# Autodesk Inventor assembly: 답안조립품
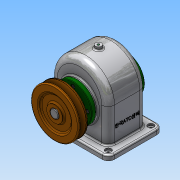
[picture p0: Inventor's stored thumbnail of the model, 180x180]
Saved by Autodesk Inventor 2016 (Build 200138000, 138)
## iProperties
Created: 2018-08
Part Number: 답안조립품
Material: 일반
Document SubType Name: Assembly
Designer: Administrator
Author: Administrator
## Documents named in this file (13)
- C:\Users\Administrator\Desktop\480811V1013\답안조립품.iam
- C:\Users\Administrator\Desktop\480811V1013\본체.ipt
- C:\Users\Administrator\Desktop\480811V1013\축.ipt
- C:\Users\Administrator\Desktop\480811V1013\베어링 6203.ipt
- C:\Users\Administrator\Desktop\480811V1013\키 6x6x22.ipt
- C:\Users\Administrator\Desktop\480811V1013\스퍼기어.ipt
- C:\Users\Administrator\Desktop\480811V1013\뒤커버.ipt
- C:\Users\Administrator\Desktop\480811V1013\앞커버.ipt
- C:\Users\Administrator\Desktop\480811V1013\오일 실 28 40 8.ipt
- C:\Users\Administrator\Desktop\480811V1013\키 5x5x18.ipt
- C:\Users\Administrator\Desktop\480811V1013\V-벨트풀리.ipt
- C:\Users\Administrator\Desktop\480811V1013\멈춤나사 M4.ipt
- C:\Users\Administrator\Desktop\480811V1013\볼트 M4.ipt
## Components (1 placed, 1 different names)
1. V-벨트풀리:1
